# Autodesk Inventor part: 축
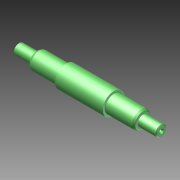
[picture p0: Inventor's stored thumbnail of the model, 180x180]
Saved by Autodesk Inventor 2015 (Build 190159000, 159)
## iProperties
Created: 2026-04
Part Number: 축
Material: 일반
Document SubType Name: Modeling
Designer: User
Density: 1 g/cm^3
Appearance: 기본값
Author: User
Author: jhkim
Creation Date: 2026-03-26
Sending System: Autodesk Inventor 2026
Preprocessor: ST-DEVELOPER v20.1
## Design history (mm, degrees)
node "축1"
node "솔리드1"
node "기준1"
